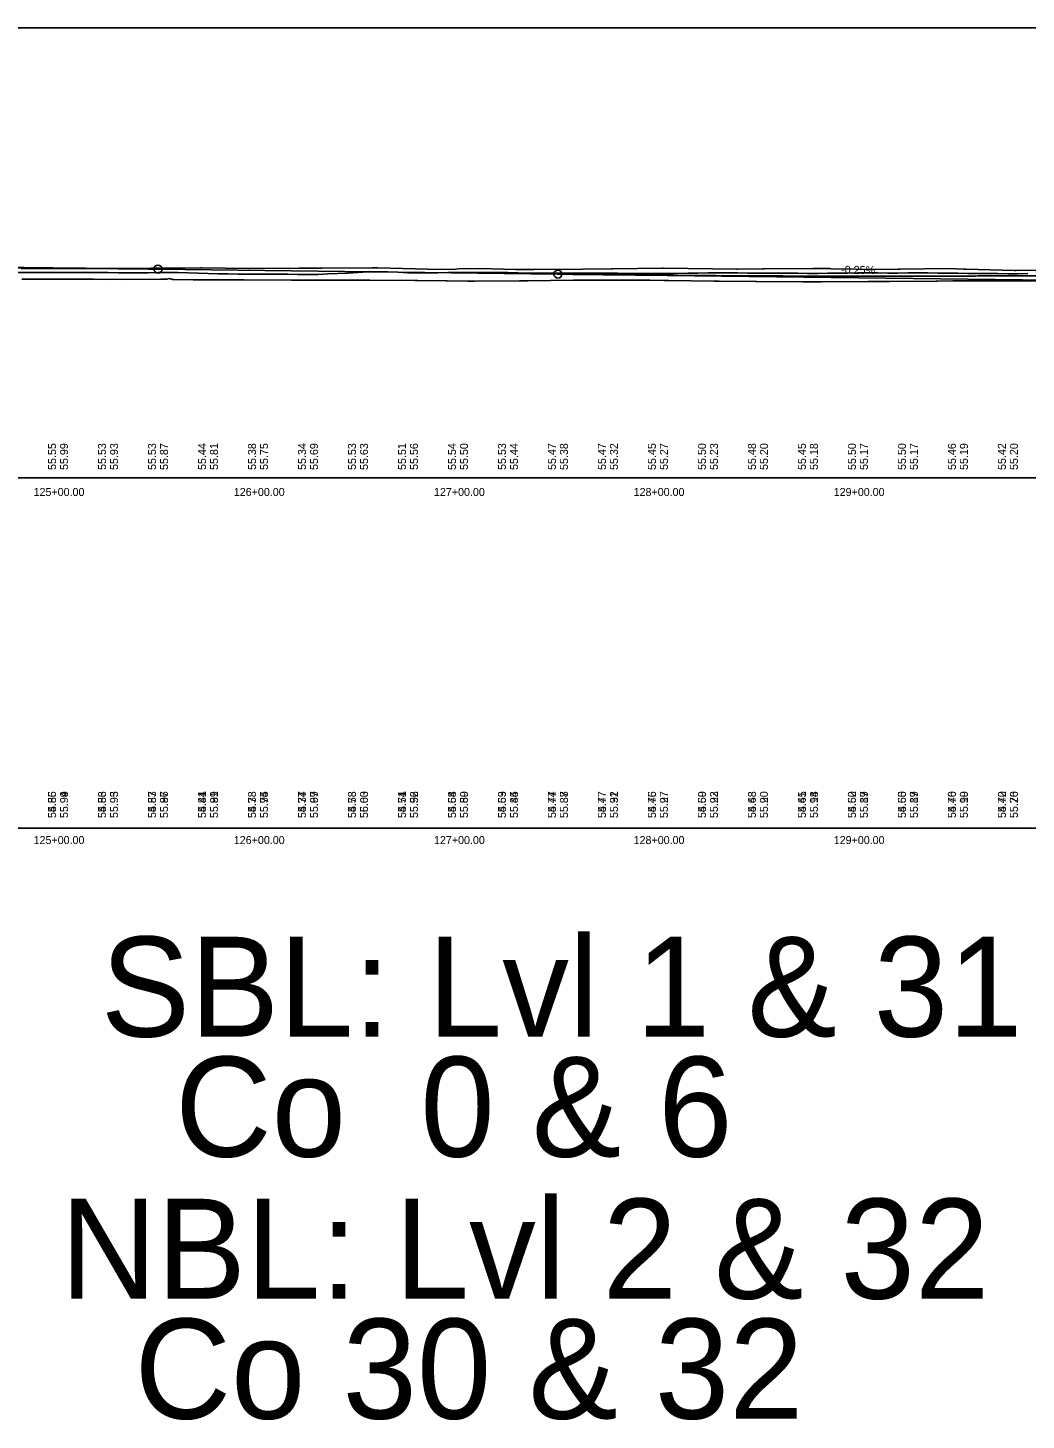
# Model space of a CAD drawing. Extents: x 3880794 to 3915434, y 287517 to 300173.
# Drawn here: x 3893023 to 3893522, y 297428 to 298124 of the extents above; entities that cross this region are included whole.
import ezdxf

# ---------------------------------------------------------------- set-up
doc = ezdxf.new("R2010")
doc.units = 0
for name, color, linetype in [('Level 1', 7, 'Continuous'), ('Level 2', 7, 'Continuous'), ('Level 30', 7, 'Continuous'), ('Level 31', 7, 'Continuous'), ('Level 32', 7, 'Continuous'), ('Level 62', 7, 'Continuous'), ('Level 63', 7, 'Continuous')]:
    doc.layers.add(name, color=color, linetype=linetype)

msp = doc.modelspace()

# ---------------------------------------------------------------- linework, layer by layer
at = {"layer": 'Level 1'}
for p, q in [((3893088.3, 298003.57), (3892842.3, 298006.64)), ((3893088.3, 298003.57), (3893288.3, 298001.07)), ((3893288.3, 298001.07), (3893534.3, 297997.99))]:
    msp.add_line(p, q, dxfattribs=at)
msp.add_lwpolyline([(3893020.14, 297998.6), (3893032.16, 297998.58), (3893039.66, 297998.5), (3893055.96, 297998.48), (3893062.85, 297998.47), (3893065.95, 297998.49), (3893070.55, 297998.43), (3893089.64, 297998.56), (3893092.66, 297998.62), (3893093.83, 297998.82), (3893095.76, 297998.44), (3893096.12, 297998.36), (3893105.81, 297998.27), (3893106.55, 297998.24), (3893107.17, 297998.2), (3893108.35, 297998.24), (3893126.87, 297998.2), (3893129.88, 297998.18), (3893131.37, 297998.16), (3893155, 297998.02), (3893155.85, 297998.04), (3893164.54, 297998.07), (3893165, 297998.04), (3893188.46, 297998.11), (3893188.85, 297998.11), (3893190.07, 297998.08), (3893192.91, 297998.06), (3893194.27, 297998.05), (3893216.73, 297997.88), (3893218.28, 297997.86), (3893232.15, 297997.66), (3893232.87, 297997.68), (3893243.1, 297997.53), (3893244.43, 297997.57), (3893246.54, 297997.56), (3893269.08, 297997.7), (3893270.85, 297997.71), (3893273.08, 297997.66), (3893296.01, 297997.98), (3893308.17, 297998.14), (3893310.7, 297998.07), (3893333.33, 297998.01), (3893334.17, 297997.98), (3893341.35, 297997.97), (3893343.54, 297997.95), (3893366.46, 297997.6), (3893366.89, 297997.6), (3893368.9, 297997.61), (3893387.24, 297997.32), (3893387.69, 297997.33), (3893410.72, 297997.2), (3893412.71, 297997.23), (3893419.67, 297997.2), (3893420.16, 297997.2), (3893443.34, 297997.33), (3893445.15, 297997.33), (3893445.5, 297997.33), (3893452.43, 297997.36), (3893454.26, 297997.35), (3893477.42, 297997.61), (3893477.87, 297997.6), (3893485.82, 297997.69), (3893487.82, 297997.7), (3893510.9, 297997.68), (3893511.21, 297997.68), (3893512.39, 297997.68), (3893513.18, 297997.69), (3893536.6, 297997.48)], dxfattribs=at)
for points in [[(3892588.3, 298003.36), (3892598.3, 298003.49), (3892608.3, 298003.61), (3892618.3, 298003.73), (3892628.3, 298003.85), (3892638.3, 298003.96), (3892648.3, 298004.06), (3892658.3, 298004.16), (3892668.3, 298004.26), (3892678.3, 298004.35), (3892688.3, 298004.43), (3892698.3, 298004.51), (3892708.3, 298004.59), (3892718.3, 298004.65), (3892728.3, 298004.72), (3892738.3, 298004.78), (3892748.3, 298004.83), (3892758.3, 298004.88), (3892768.3, 298004.92), (3892778.3, 298004.96), (3892788.3, 298004.99), (3892798.3, 298005.02), (3892808.3, 298005.04), (3892818.3, 298005.06), (3892828.3, 298005.07), (3892838.3, 298005.08), (3892848.3, 298005.08), (3892858.3, 298005.07), (3892868.3, 298005.07), (3892878.3, 298005.05), (3892888.3, 298005.03), (3892898.3, 298005.01), (3892908.3, 298004.98), (3892918.3, 298004.94), (3892928.3, 298004.9), (3892938.3, 298004.86), (3892948.3, 298004.81), (3892958.3, 298004.75), (3892968.3, 298004.69), (3892978.3, 298004.63), (3892988.3, 298004.56), (3892998.3, 298004.48), (3893008.3, 298004.4), (3893018.3, 298004.31), (3893028.3, 298004.22), (3893038.3, 298004.13), (3893048.3, 298004.02), (3893058.3, 298003.92), (3893068.3, 298003.8), (3893078.3, 298003.69), (3893088.3, 298003.57)], [(3893288.3, 298001.07), (3893298.3, 298000.94), (3893308.3, 298000.83), (3893318.3, 298000.73), (3893328.3, 298000.63), (3893338.3, 298000.54), (3893348.3, 298000.46), (3893358.3, 298000.38), (3893368.3, 298000.31), (3893378.3, 298000.25), (3893388.3, 298000.2), (3893398.3, 298000.16), (3893408.3, 298000.12), (3893418.3, 298000.1), (3893428.3, 298000.08), (3893438.3, 298000.06), (3893448.3, 298000.06), (3893458.3, 298000.06), (3893468.3, 298000.07), (3893478.3, 298000.09), (3893488.3, 298000.11), (3893498.3, 298000.15), (3893508.3, 298000.19), (3893518.3, 298000.24), (3893528.3, 298000.3), (3893538.3, 298000.36), (3893548.3, 298000.43), (3893558.3, 298000.52), (3893568.3, 298000.6), (3893578.3, 298000.7), (3893588.3, 298000.8), (3893598.3, 298000.91), (3893608.3, 298001.03), (3893618.3, 298001.16), (3893628.3, 298001.29), (3893638.3, 298001.44), (3893648.3, 298001.59), (3893658.3, 298001.74), (3893668.3, 298001.91), (3893678.3, 298002.08), (3893688.3, 298002.27), (3893698.3, 298002.45), (3893708.3, 298002.65), (3893718.3, 298002.85), (3893728.3, 298003.07), (3893738.3, 298003.29), (3893748.3, 298003.52), (3893758.3, 298003.75), (3893768.3, 298003.99), (3893778.3, 298004.24), (3893788.3, 298004.5)]]:
    msp.add_spline(points, degree=3, dxfattribs=at)
at = {"layer": 'Level 2'}
for p, q in [((3893019.92, 298003.72), (3893044.69, 298003.93)), ((3893044.69, 298003.93), (3893046.31, 298003.94)), ((3893046.31, 298003.94), (3893054.46, 298003.95)), ((3893054.46, 298003.95), (3893071.2, 298003.97)), ((3893071.2, 298003.97), (3893084.66, 298003.98)), ((3893084.66, 298003.98), (3893085.12, 298003.98)), ((3893085.12, 298003.98), (3893109.58, 298004.2)), ((3893109.58, 298004.2), (3893110.14, 298004.18)), ((3893110.14, 298004.18), (3893133.55, 298003.87)), ((3893133.55, 298003.87), (3893133.89, 298003.87)), ((3893133.89, 298003.87), (3893158.8, 298004.02)), ((3893158.8, 298004.02), (3893170.42, 298004.1)), ((3893170.42, 298004.1), (3893195.28, 298004.2)), ((3893195.28, 298004.2), (3893198.05, 298004.21)), ((3893198.05, 298004.21), (3893223, 298003.56)), ((3893223, 298003.56), (3893227.24, 298003.45)), ((3893227.24, 298003.45), (3893237.19, 298003.63)), ((3893237.19, 298003.63), (3893238.47, 298003.65)), ((3893238.47, 298003.65), (3893249.04, 298003.83)), ((3893249.04, 298003.83), (3893267.08, 298003.34)), ((3893267.08, 298003.34), (3893267.75, 298003.37)), ((3893267.75, 298003.37), (3893275.67, 298003.43)), ((3893275.67, 298003.43), (3893276.27, 298003.43)), ((3893276.27, 298003.43), (3893300.72, 298003.62)), ((3893300.72, 298003.62), (3893315.22, 298003.78)), ((3893315.22, 298003.78), (3893315.72, 298003.78)), ((3893315.72, 298003.78), (3893340.33, 298004.04)), ((3893340.33, 298004.04), (3893340.99, 298004.04)), ((3893340.99, 298004.04), (3893353.36, 298003.9)), ((3893353.36, 298003.9), (3893377.77, 298003.62)), ((3893377.77, 298003.62), (3893378.35, 298003.62)), ((3893378.35, 298003.62), (3893390.73, 298003.73)), ((3893390.73, 298003.73), (3893391.34, 298003.72)), ((3893391.34, 298003.72), (3893415.9, 298003.94)), ((3893415.9, 298003.94), (3893424.32, 298003.82)), ((3893424.32, 298003.82), (3893424.98, 298003.81)), ((3893424.98, 298003.81), (3893449.41, 298003.46)), ((3893449.41, 298003.46), (3893458.6, 298003.57)), ((3893458.6, 298003.57), (3893459.46, 298003.57)), ((3893459.46, 298003.57), (3893483.54, 298003.85)), ((3893483.54, 298003.85), (3893491.22, 298003.62)), ((3893491.22, 298003.62), (3893492.45, 298003.61)), ((3893492.45, 298003.61), (3893516.6, 298002.87)), ((3893516.6, 298002.87), (3893517.5, 298002.85)), ((3893517.5, 298002.85), (3893528.35, 298003.02))]:
    msp.add_line(p, q, dxfattribs=at)
for points in [[(3893038.3, 298001.96), (3893043.3, 298001.96), (3893048.3, 298001.95), (3893053.3, 298001.91), (3893058.3, 298001.88), (3893063.3, 298001.84), (3893068.3, 298001.81), (3893073.3, 298001.78), (3893078.3, 298001.75), (3893083.3, 298001.8), (3893088.3, 298001.85), (3893093.3, 298001.91), (3893098.3, 298001.9), (3893103.3, 298001.69), (3893108.3, 298001.54), (3893113.3, 298001.4), (3893118.3, 298001.25), (3893123.3, 298001.17), (3893128.3, 298001.14), (3893133.3, 298001.12), (3893138.3, 298001.09), (3893143.3, 298001.07), (3893148.3, 298001.03), (3893153.3, 298000.98), (3893158.3, 298000.92), (3893163.3, 298000.87), (3893168.3, 298000.91), (3893173.3, 298001.15), (3893178.3, 298001.37), (3893183.3, 298001.6), (3893188.3, 298001.82), (3893193.3, 298002.22), (3893198.3, 298002.21), (3893203.3, 298002.3), (3893208.3, 298002.09), (3893213.3, 298001.75), (3893218.3, 298001.76), (3893223.3, 298001.68), (3893228.3, 298001.73), (3893233.3, 298001.82), (3893238.3, 298001.91), (3893243.3, 298001.89), (3893248.3, 298001.86), (3893253.3, 298001.85), (3893258.3, 298001.84), (3893263.3, 298001.83), (3893268.3, 298001.69), (3893273.3, 298001.62), (3893278.3, 298001.57), (3893283.3, 298001.57), (3893288.3, 298001.56), (3893293.3, 298001.56), (3893298.3, 298001.56), (3893303.3, 298001.56), (3893308.3, 298001.56), (3893313.3, 298001.55), (3893318.3, 298001.5), (3893323.3, 298001.46), (3893328.3, 298001.46), (3893333.3, 298001.46), (3893338.3, 298001.45), (3893343.3, 298001.44), (3893348.3, 298001.44), (3893353.3, 298001.5), (3893358.3, 298001.58), (3893363.3, 298001.67), (3893368.3, 298001.69), (3893373.3, 298001.69), (3893378.3, 298001.68), (3893383.3, 298001.64), (3893388.3, 298001.59), (3893393.3, 298001.56), (3893398.3, 298001.54), (3893403.3, 298001.5), (3893408.3, 298001.48), (3893413.3, 298001.46), (3893418.3, 298001.44), (3893423.3, 298001.5), (3893428.3, 298001.57), (3893433.3, 298001.64), (3893438.3, 298001.67), (3893443.3, 298001.71), (3893448.3, 298001.68), (3893453.3, 298001.64), (3893458.3, 298001.64), (3893463.3, 298001.67), (3893468.3, 298001.7), (3893473.3, 298001.66), (3893478.3, 298001.61), (3893483.3, 298001.56), (3893488.3, 298001.51), (3893493.3, 298001.47), (3893498.3, 298001.42), (3893503.3, 298001.37), (3893508.3, 298001.32), (3893513.3, 298001.27), (3893518.3, 298001.29), (3893523.3, 298001.32)], [(3893018.3, 298001.95), (3893023.3, 298001.95), (3893028.3, 298001.96), (3893033.3, 298001.96), (3893038.3, 298001.96)]]:
    msp.add_lwpolyline(points, dxfattribs=at)
at = {"layer": 'Level 31'}
for centre in [(3893088.3, 298003.57), (3893288.3, 298001.07)]:
    msp.add_circle(centre, 2, dxfattribs=at)
at = {"layer": 'Level 62'}
msp.add_lwpolyline([(3892938.3, 297899.19), (3893638.3, 297899.19), (3893638.3, 298124.19), (3892938.3, 298124.19)], close=True, dxfattribs=at)
msp.add_lwpolyline([(3892938.3, 297899.19), (3893638.3, 297899.19), (3893638.3, 298124.19), (3892938.3, 298124.19)], close=True, dxfattribs=at)
at = {"layer": 'Level 63'}
msp.add_line((3881538.3, 297724.19), (3896411.35, 297724.19), dxfattribs=at)

# ---------------------------------------------------------------- texts
at = {"layer": 'Level 1'}
for s, p in [('SBL: Lvl 1 & 31', (3893059.7, 297619.9)), ('  Co  0 & 6', (3893059.7, 297559.9))]:
    msp.add_text(s, height=50, dxfattribs=at).set_placement(p)
at = {"layer": 'Level 2'}
for s, p in [('NBL: Lvl 2 & 32', (3893039.4, 297488.93)), ('  Co 30 & 32', (3893039.4, 297428.93))]:
    msp.add_text(s, height=50, dxfattribs=at).set_placement(p)
at = {"layer": 'Level 30'}
for s, p in [('125+00.00', (3893026.08, 297890.19)), ('125+00.00', (3893026.08, 297890.19)), ('126+00.00', (3893126.2, 297890.19)), ('126+00.00', (3893126.2, 297890.19)), ('127+00.00', (3893226.3, 297890.19)), ('127+00.00', (3893226.3, 297890.19)), ('128+00.00', (3893326.14, 297890.19)), ('128+00.00', (3893326.14, 297890.19)), ('129+00.00', (3893426.2, 297890.19)), ('129+00.00', (3893426.2, 297890.19)), ('125+00.00', (3893026.08, 297716.19)), ('125+00.00', (3893026.08, 297716.19)), ('126+00.00', (3893126.2, 297716.19)), ('126+00.00', (3893126.2, 297716.19)), ('127+00.00', (3893226.3, 297716.19)), ('127+00.00', (3893226.3, 297716.19)), ('128+00.00', (3893326.14, 297716.19)), ('128+00.00', (3893326.14, 297716.19)), ('129+00.00', (3893426.2, 297716.19)), ('129+00.00', (3893426.2, 297716.19))]:
    msp.add_text(s, height=4, dxfattribs=at).set_placement(p)
at = {"layer": 'Level 31'}
for s, rotation, p in [('-0.25%', 359.28384, (3893429.92, 298001.29)), ('55.99', 90, (3893043.3, 297903.19)), ('55.93', 90, (3893068.3, 297903.19)), ('55.87', 90, (3893093.3, 297903.19)), ('55.81', 90, (3893118.3, 297903.19)), ('55.75', 90, (3893143.3, 297903.19)), ('55.69', 90, (3893168.3, 297903.19)), ('55.63', 90, (3893193.3, 297903.19)), ('55.56', 90, (3893218.3, 297903.19)), ('55.50', 90, (3893243.3, 297903.19)), ('55.44', 90, (3893268.3, 297903.19)), ('55.38', 90, (3893293.3, 297903.19)), ('55.32', 90, (3893318.3, 297903.19)), ('55.27', 90, (3893343.3, 297903.19)), ('55.23', 90, (3893368.3, 297903.19)), ('55.20', 90, (3893393.3, 297903.19)), ('55.18', 90, (3893418.3, 297903.19)), ('55.17', 90, (3893443.3, 297903.19)), ('55.17', 90, (3893468.3, 297903.19)), ('55.19', 90, (3893493.3, 297903.19)), ('55.20', 90, (3893518.3, 297903.19)), ('54.86', 90, (3893037.3, 297729.19)), ('55.99', 90, (3893043.3, 297729.19)), ('54.86', 90, (3893062.3, 297729.19)), ('55.93', 90, (3893068.3, 297729.19)), ('54.87', 90, (3893087.3, 297729.19)), ('55.87', 90, (3893093.3, 297729.19)), ('54.81', 90, (3893112.3, 297729.19)), ('55.81', 90, (3893118.3, 297729.19)), ('54.78', 90, (3893137.3, 297729.19)), ('55.75', 90, (3893143.3, 297729.19)), ('54.77', 90, (3893162.3, 297729.19)), ('55.69', 90, (3893168.3, 297729.19)), ('54.78', 90, (3893187.3, 297729.19)), ('55.63', 90, (3893193.3, 297729.19)), ('54.74', 90, (3893212.3, 297729.19)), ('55.56', 90, (3893218.3, 297729.19)), ('54.68', 90, (3893237.3, 297729.19)), ('55.50', 90, (3893243.3, 297729.19)), ('54.69', 90, (3893262.3, 297729.19)), ('55.44', 90, (3893268.3, 297729.19)), ('54.74', 90, (3893287.3, 297729.19)), ('55.38', 90, (3893293.3, 297729.19)), ('54.77', 90, (3893312.3, 297729.19)), ('55.32', 90, (3893318.3, 297729.19)), ('54.76', 90, (3893337.3, 297729.19)), ('55.27', 90, (3893343.3, 297729.19)), ('54.69', 90, (3893362.3, 297729.19)), ('55.23', 90, (3893368.3, 297729.19)), ('54.63', 90, (3893387.3, 297729.19)), ('55.20', 90, (3893393.3, 297729.19)), ('54.61', 90, (3893412.3, 297729.19)), ('55.18', 90, (3893418.3, 297729.19)), ('54.62', 90, (3893437.3, 297729.19)), ('55.17', 90, (3893443.3, 297729.19)), ('54.65', 90, (3893462.3, 297729.19)), ('55.17', 90, (3893468.3, 297729.19)), ('54.70', 90, (3893487.3, 297729.19)), ('55.19', 90, (3893493.3, 297729.19)), ('54.70', 90, (3893512.3, 297729.19)), ('55.20', 90, (3893518.3, 297729.19))]:
    msp.add_text(s, height=4, rotation=rotation, dxfattribs=at).set_placement(p)
at = {"layer": 'Level 32'}
for s, p in [('55.55', (3893037.3, 297903.19)), ('55.53', (3893062.3, 297903.19)), ('55.53', (3893087.3, 297903.19)), ('55.44', (3893112.3, 297903.19)), ('55.38', (3893137.3, 297903.19)), ('55.34', (3893162.3, 297903.19)), ('55.53', (3893187.3, 297903.19)), ('55.51', (3893212.3, 297903.19)), ('55.54', (3893237.3, 297903.19)), ('55.53', (3893262.3, 297903.19)), ('55.47', (3893287.3, 297903.19)), ('55.47', (3893312.3, 297903.19)), ('55.45', (3893337.3, 297903.19)), ('55.50', (3893362.3, 297903.19)), ('55.48', (3893387.3, 297903.19)), ('55.45', (3893412.3, 297903.19)), ('55.50', (3893437.3, 297903.19)), ('55.50', (3893462.3, 297903.19)), ('55.46', (3893487.3, 297903.19)), ('55.42', (3893512.3, 297903.19)), ('55.55', (3893037.3, 297729.19)), ('55.94', (3893043.3, 297729.19)), ('55.53', (3893062.3, 297729.19)), ('55.95', (3893068.3, 297729.19)), ('55.53', (3893087.3, 297729.19)), ('55.96', (3893093.3, 297729.19)), ('55.44', (3893112.3, 297729.19)), ('55.99', (3893118.3, 297729.19)), ('55.38', (3893137.3, 297729.19)), ('55.94', (3893143.3, 297729.19)), ('55.34', (3893162.3, 297729.19)), ('55.97', (3893168.3, 297729.19)), ('55.53', (3893187.3, 297729.19)), ('56.00', (3893193.3, 297729.19)), ('55.51', (3893212.3, 297729.19)), ('55.92', (3893218.3, 297729.19)), ('55.54', (3893237.3, 297729.19)), ('55.89', (3893243.3, 297729.19)), ('55.53', (3893262.3, 297729.19)), ('55.85', (3893268.3, 297729.19)), ('55.47', (3893287.3, 297729.19)), ('55.87', (3893293.3, 297729.19)), ('55.47', (3893312.3, 297729.19)), ('55.91', (3893318.3, 297729.19)), ('55.45', (3893337.3, 297729.19)), ('55.97', (3893343.3, 297729.19)), ('55.50', (3893362.3, 297729.19)), ('55.92', (3893368.3, 297729.19)), ('55.48', (3893387.3, 297729.19)), ('55.90', (3893393.3, 297729.19)), ('55.45', (3893412.3, 297729.19)), ('55.94', (3893418.3, 297729.19)), ('55.50', (3893437.3, 297729.19)), ('55.89', (3893443.3, 297729.19)), ('55.50', (3893462.3, 297729.19)), ('55.89', (3893468.3, 297729.19)), ('55.46', (3893487.3, 297729.19)), ('55.90', (3893493.3, 297729.19)), ('55.42', (3893512.3, 297729.19)), ('55.76', (3893518.3, 297729.19))]:
    msp.add_text(s, height=4, rotation=90, dxfattribs=at).set_placement(p)

doc.saveas('drawing.dxf')
